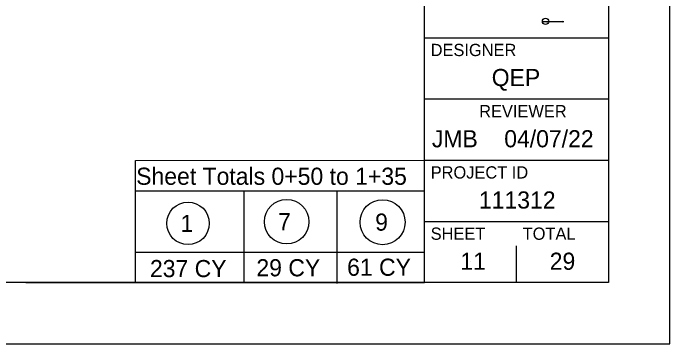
# Model space of a CAD drawing. Extents: x -149 to 57, y 0 to 22.
# Drawn here: x 28.65 to 34, y 0 to 2.7 of the extents above; entities that cross this region are included whole.
import ezdxf

# ---------------------------------------------------------------- set-up
doc = ezdxf.new("R2010")
doc.units = 0
for name, color, linetype in [('CS-ALGN-TEXT', 7, 'Continuous'), ('CS-ANNO', 7, 'Continuous'), ('CS-ANNO-MATC', 7, 'Continuous'), ('CS-ANNO-MATC-TEXT', 7, 'Continuous'), ('CS-ANNO-TABL', 7, 'Continuous')]:
    doc.layers.add(name, color=color, linetype=linetype)

msp = doc.modelspace()

# ---------------------------------------------------------------- linework, layer by layer
at = {"layer": 'CS-ALGN-TEXT'}
for p, q in [((29.644, 1.4971), (32, 1.5)), ((29.644, 0.4971), (29.644, 1.4971)), ((29.644, 1.25), (32, 1.25)), ((30.5289, 0.5011), (30.5289, 1.2511)), ((31.2887, 0.4933), (31.2887, 1.2433)), ((29.644, 0.75), (32, 0.75)), ((32.75, 0.5), (32.75, 0.8)), ((32.375, 0.675), (32.375, 0.675)), ((28.75, 0.5), (32, 0.5))]:
    msp.add_line(p, q, dxfattribs=at)
at = {"layer": 'CS-ANNO'}
msp.add_lwpolyline([(0, 0), (34, 0), (34, 22), (0, 22)], close=True, dxfattribs=at)
at = {"layer": 'CS-ANNO-MATC'}
for p, q in [((32, 0.5), (32, 21.5)), ((32, 2.5), (33.5, 2.5)), ((32, 2), (33.5, 2)), ((32, 1.5), (33.5, 1.5)), ((32, 1), (33.5, 1))]:
    msp.add_line(p, q, dxfattribs=at)
msp.add_lwpolyline([(1.5, 21.5), (33.5, 21.5), (33.5, 0.5), (1.5, 0.5)], close=True, dxfattribs=at)
at = {"layer": 'CS-ANNO-MATC-TEXT'}
for centre, radius in [((30.8764, 0.9975), 0.1813), ((30.0716, 0.984), 0.1737), ((31.6579, 0.9933), 0.1837)]:
    msp.add_circle(centre, radius, dxfattribs=at)
at = {"layer": 'CS-ANNO-TABL'}
for p, q in [((32.9603, 2.6333), (33.0124, 2.6333)), ((32.9866, 2.6333), (33.1345, 2.6333))]:
    msp.add_line(p, q, dxfattribs=at)
msp.add_circle((32.9863, 2.6333), 0.026, dxfattribs=at)

# ---------------------------------------------------------------- texts
at = {"layer": 'CS-ALGN-TEXT'}
for s, height, p in [('DESIGNER', 0.1, (32.05, 2.35)), ('QEP', 0.14, (32.5477, 2.105)), ('REVIEWER', 0.1, (32.4454, 1.85)), ('JMB', 0.14, (32.0596, 1.605)), ('04/07/22', 0.14, (32.6497, 1.605)), ('Sheet Totals 0+50 to 1+35', 0.14, (29.6493, 1.2989)), ('PROJECT ID', 0.1, (32.05, 1.35)), ('111312', 0.14, (32.4435, 1.105)), ('SHEET', 0.1, (32.05, 0.85)), ('TOTAL', 0.1, (32.8, 0.85)), ('11', 0.14, (32.2915, 0.605)), ('29', 0.14, (33.0206, 0.605))]:
    msp.add_text(s, height=height, dxfattribs=at).set_placement(p)
at = {"layer": 'CS-ANNO-MATC-TEXT'}
for s, p in [('1', (30.0104, 0.9137)), ('7', (30.8063, 0.9284)), ('9', (31.5974, 0.9243)), ('61 CY', (31.3688, 0.5561)), ('237 CY', (29.7614, 0.5449)), ('29 CY', (30.6292, 0.5516))]:
    msp.add_text(s, height=0.14, dxfattribs=at).set_placement(p)
at = {"layer": 'CS-ANNO-TABL'}
for s, p in [('1+00.00', (32.9783, 2.6235)), ('2', (32.9852, 2.6399)), ('Drawing', (33.1175, 2.6399)), ('1:2', (33.1175, 2.6235))]:
    msp.add_text(s, height=0.00328, dxfattribs=at).set_placement(p)

doc.saveas('drawing.dxf')
